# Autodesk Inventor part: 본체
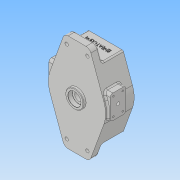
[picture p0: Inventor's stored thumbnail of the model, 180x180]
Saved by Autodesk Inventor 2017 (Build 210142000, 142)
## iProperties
Part Number: 본체
Material: 일반
Document SubType Name: Modeling
Designer: MRC
Density: 1 g/cm^3
Appearance: 기본값
Author: MRC
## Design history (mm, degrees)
sketch "스케치1"
  geometry: L1 (-51.683, 18.811)-(-33.78, 68); L2 (-24.317, 94)-(0, 94); L3 (0, 0)-(0, 94); L4 (0, 0)-(-58.53, 0); L5 (51.683, 18.811)-(33.78, 68); L6 (24.317, 94)-(0, 94); L7 (-51.683, -18.811)-(-33.78, -68); L8 (-24.317, -94)-(0, -94); L9 (51.683, -18.811)-(33.78, -68); L10 (24.317, -94)-(0, -94); L11 (-33.78, 68)-(33.78, 68); L12 (-33.78, -68)-(33.78, -68); L13 (-33.78, 68)-(-24.317, 94); L14 (33.78, 68)-(24.317, 94); L15 (33.78, -68)-(24.317, -94); L16 (-33.78, -68)-(-24.317, -94); A1 r 55 centre (0, 0) between (-51.683, 18.811) and (-51.683, -18.811); A2 r 55 centre (0, 0) between (51.683, -18.811) and (51.683, 18.811); 1 further point
  constraints: 32 end point, 8 tangent, 4 point on circle, 4 symmetric about line, 3 horizontal, 2 centre point, 1 coincident, 1 parallel, 1 vertical, 1 vertical alignment
  dimensions: "d3" = 20 deg angle of L3 L1; "d4" = 94 distance from line of point (0, 0) L2; "d6" = 136 distance between parallel lines of L12 L11; "d7" = 68 distance from line of L11 point (0, 0); "d8" = 55 radius of A2; "d9" = 55 radius of A1
extrude "돌출1" new body sketch "스케치1" distance "d10" = 15; taper "d11" = 0 deg
extrude "돌출2" join sketch "스케치1" distance "d12" = 55; taper "d13" = 0 deg
sketch "스케치3"
  geometry: C1 r 17.5 at (0, 0); A1 r 55 centre (0, 0) between (-51.683, 18.811) and (-51.683, -18.811) reference
  constraints: 1 centre point, 1 coincident
  dimensions: "d22" = 35 diameter of C1
extrude "돌출4" join sketch "스케치3" distance "d23" = 5; taper "d24" = 0 deg
sketch "스케치4"
  geometry: L1 (-68, 15)-(-68, 55) reference; L2 (-68, 55)-(68, 55) reference; L3 (68, 55)-(68, 15) reference; L4 (68, 15)-(94, 15) reference; L5 (94, 15)-(94, 0) reference; L6 (94, 0)-(17.5, 0) reference; L7 (17.5, 0)-(17.5, -5) reference; L8 (17.5, -5)-(-17.5, -5) reference; L9 (-17.5, -5)-(-17.5, 0) reference; L10 (-17.5, 0)-(-94, 0) reference; L11 (-94, 0)-(-94, 15) reference; L12 (-94, 15)-(-68, 15) reference; L13 (-9, 5)-(27, 5); L14 (32, 10)-(32, 30); L15 (27, 35)-(-9, 35); L16 (-14, 30)-(-14, 10); L17 (9, 5)-(9, 35); A1 r 5 centre (27, 30) between (32, 30) and (27, 35); A2 r 5 centre (-9, 30) between (-9, 35) and (-14, 30); A3 r 5 centre (-9, 10) between (-14, 10) and (-9, 5); A4 r 5 centre (27, 10) between (27, 5) and (32, 10); 4 further points
  constraints: 10 end point, 8 point on circle, 8 tangent, 6 point on line, 4 centre point, 3 equal radius, 2 midpoint, 2 parallel, 1 horizontal, 1 perpendicular
  dimensions: "d25" = 9 distance from line of point (0, 0) L17; "d26" = 30 distance of point (32, 5) point (32, 35); "d27" = 46 distance of point (32, 35) point (-14, 35); "d28" = 5 distance between parallel lines of L13 L6; "d29" = 5 radius of A1 (derived)
extrude "돌출5" join sketch "스케치4" stored distance "d30" = 118; taper "d31" = 0 deg
sketch "스케치5"
  geometry: A1 r 55 centre (0, 0) between (51.683, -18.811) and (51.683, 18.811) reference; 1 further point
  constraints: 1 vertical alignment
  dimensions: "d32" = 9 distance of A1.centre point (0, 9)
hole "구멍1" sketch "스케치5" at (0, 9) diameter "d33" = 80; stored, may be unused: countersink angle "d37" = 90 deg, drill point angle "d39" = 0 deg; dims "d34" = 6, "d35" = 4, "d36" = 2, "d38" = 30
node "작업 평면1"
sketch "스케치6"
  geometry: L1 (-40, 55)-(40, 55) reference; L2 (0, 55)-(0, 28.705); L3 (-33.78, 55)-(-51.683, 55) reference; L4 (-47.5, 55)-(-47.5, 53.1); L5 (-47, 52.6)-(-43.9, 52.6); L6 (-43.4, 53.1)-(-43.4, 55); L7 (-43.4, 55)-(-47.5, 55); A1 r 0.5 centre (-43.9, 53.1) between (-43.9, 52.6) and (-43.4, 53.1); A2 r 0.5 centre (-47, 53.1) between (-47.5, 53.1) and (-47, 52.6); 2 further points
  constraints: 10 end point, 4 point on circle, 4 point on line, 4 tangent, 3 perpendicular, 2 centre point, 2 vertical, 1 equal radius, 1 midpoint
  dimensions: "d41" = 95 diameter of L4 L2; "d42" = 4.1 distance between parallel lines of L4 L6; "d43" = 2.4 distance of point (-43.4, 52.6) L6.end; "d44" = 0.5 radius of A1
revolve "회전1" sketch "스케치6" stored, may be unused: angle "d45" = 90 deg
sketch "스케치7"
  geometry: L1 (17.5, 0)-(17.5, -5) reference; L2 (17.5, -5)-(-17.5, -5) reference; L3 (-17.5, -5)-(-17.5, 0) reference; L4 (-17.5, 0)-(-94, 0) reference; L5 (-94, 0)-(-94, 15) reference; L6 (-94, 15)-(-68, 15) reference; L7 (-68, 15)-(-68, 55) reference; L8 (-68, 55)-(-38.5, 55) reference; L9 (-38.5, 55)-(-38.5, 53.1) reference; L10 (-38, 52.6)-(-34.9, 52.6) reference; L11 (-34.4, 53.1)-(-34.4, 55) reference; L12 (-34.4, 55)-(-31, 55) reference; L13 (-31, 55)-(-31, 25) reference; L14 (-31, 25)-(49, 25) reference; L15 (49, 25)-(49, 55) reference; L16 (49, 55)-(52.4, 55) reference; L17 (52.4, 55)-(52.4, 53.1) reference; L18 (52.9, 52.6)-(56, 52.6) reference; L19 (56.5, 53.1)-(56.5, 55) reference; L20 (56.5, 55)-(68, 55) reference; L21 (68, 55)-(68, 15) reference; L22 (68, 15)-(94, 15) reference; L23 (94, 15)-(94, 0) reference; L24 (94, 0)-(17.5, 0) reference; L25 (49, 25)-(-31, 25) reference; L26 (0, 25)-(0, -5); L27 (0, 25)-(10, 25); L28 (10, 25)-(10, 15); L29 (10, 15)-(8, 15); L30 (8, 15)-(8, 3.4); L31 (-9, 5)-(18.811, 5) reference; L32 (8, 3.4)-(12.3, 3.4); L33 (12.5, 3.2)-(12.5, -5); L34 (0, -5)-(12.5, -5); L35 (-17.5, -5)-(17.5, -5) reference; L36 (10, 25)-(0, 25); A1 r 0.5 centre (-38, 53.1) between (-38.5, 53.1) and (-38, 52.6) reference; A2 r 0.5 centre (-34.9, 53.1) between (-34.9, 52.6) and (-34.4, 53.1) reference; A3 r 0.5 centre (52.9, 53.1) between (52.4, 53.1) and (52.9, 52.6) reference; A4 r 0.5 centre (56, 53.1) between (56, 52.6) and (56.5, 53.1) reference; A5 r 0.2 centre (12.3, 3.2) between (12.5, 3.2) and (12.3, 3.4); 2 further points
  constraints: 18 end point, 5 point on line, 4 perpendicular, 2 point on circle, 2 tangent, 2 vertical, 1 centre point, 1 collinear, 1 midpoint, 1 parallel
  dimensions: "d46" = 20 diameter of L28 L26; "d47" = 16 diameter of L30 L26; "d48" = 25 diameter of L33 L26; "d49" = 10 distance of L27.end L28.end; "d50" = 8.4 distance of point (12.5, 3.4) L33.end; "d51" = 0.2 radius of A5
revolve "회전2" sketch "스케치7" stored, may be unused: angle "d52" = 90 deg
chamfer "모따기1" distance "d53" = 0.4; stored, may be unused: second distance "d54" = 2, angle "d55" = 30 deg
sketch "스케치8"
  geometry: L1 (-26.702, 6)-(-22.517, 6); L2 (-26.702, -6)-(-25.515, -6); L3 (-23.812, -6)-(23.812, -6); L4 (-18.735, 6)-(18.735, 6); L5 (22.517, 6)-(26.702, 6); L6 (25.515, -6)-(26.702, -6); C1 r 40 at (0, 0) reference; C2 r 8 at (0, -9) reference; A1 r 29 centre (0, 0) between (-28.373, -6) and (28.373, -6); A2 r 24 centre (0, -9) between (-20.785, 3) and (-23.552, -4.385); A3 r 29 centre (0, 0) between (-28.68, 4.296) and (-28.68, -4.296); A4 r 24 centre (0, -9) between (18.735, 6) and (-18.735, 6); A5 r 29 centre (0, 0) between (28.373, 6) and (-28.373, 6); A6 r 29 centre (0, 0) between (28.68, -4.296) and (28.68, 4.296); A7 r 24 centre (0, -9) between (23.552, -4.385) and (20.785, 3); A8 r 24 centre (0, -9) between (-23.812, -6) and (23.812, -6); A9 r 2 centre (-22.517, 4) between (-20.785, 3) and (-22.517, 6); A10 r 2 centre (-26.702, 4) between (-26.702, 6) and (-28.68, 4.296); A11 r 2 centre (-26.702, -4) between (-28.68, -4.296) and (-26.702, -6); A12 r 2 centre (-25.515, -4) between (-25.515, -6) and (-23.552, -4.385); A13 r 2 centre (25.515, -4) between (23.552, -4.385) and (25.515, -6); A14 r 2 centre (26.702, -4) between (26.702, -6) and (28.68, -4.296); A15 r 2 centre (26.702, 4) between (28.68, 4.296) and (26.702, 6); A16 r 2 centre (22.517, 4) between (22.517, 6) and (20.785, 3)
  constraints: 42 point on circle, 16 centre point, 16 tangent, 12 end point, 8 point on line, 7 equal radius, 6 horizontal, 2 coincident
  dimensions: "d56" = 58 diameter of A1; "d57" = 48 diameter of A2; "d58" = 6 distance from line of L2 C1.centre; "d59" = 6 distance from line of C1.centre L1; "d60" = 2 radius of A9
extrude "돌출6" cut sketch "스케치8" distance "d61" = 12; taper "d62" = 0 deg
sketch "스케치9"
  geometry: L1 (-5, -9)-(-5, 27) reference; L2 (-29, -8)-(-11, -8); L3 (-11, -8)-(-11, 26); L4 (-11, 26)-(-29, 26); L5 (-29, 26)-(-29, -8); L6 (-29, -8)-(-11, 26); L7 (-11, -8)-(-29, 26); 7 further points
  constraints: 12 end point, 5 coincident, 2 midpoint, 2 parallel, 1 horizontal, 1 perpendicular
  dimensions: "d63" = 9 vertical distance of point (0, 0) point (-20, 9); "d64" = 15 distance from line of L1 point (-20, 9); "d65" = 18 distance of L3.end L4.end; "d66" = 34 distance of L2.end L3.end
hole "구멍2" sketch "스케치9" diameter "d67" = 3.242; stored, may be unused: countersink angle "d71" = 90 deg, drill point angle "d73" = 118 deg; dims "d68" = 8, "d69" = 4, "d70" = 2, "d72" = 10
hole "구멍3" sketch "스케치9" diameter "d74" = 6; stored, may be unused: countersink angle "d78" = 90 deg, drill point angle "d80" = 118 deg; dims "d75" = 8, "d76" = 4, "d77" = 2, "d79" = 10
sketch "스케치10"
  geometry: A1 r 29 centre (0, 0) between (-28.68, 4.296) and (-28.68, -4.296) reference; 2 further points
  constraints: 1 horizontal alignment
  dimensions: "d81" = 30 distance of point (15, 17) point (-15, 17); "d82" = 17 vertical distance of A1.centre point (15, 17); "d83" = 15 horizontal distance of A1.centre point (-15, 17)
hole "구멍4" sketch "스케치10" at (-15, 17), (15, 17) diameter "d84" = 3.242; stored, may be unused: countersink angle "d88" = 90 deg, drill point angle "d90" = 118 deg; dims "d85" = 8, "d86" = 4, "d87" = 2, "d89" = 10
sketch "스케치11"
  geometry: L1 (-22.517, 15)-(-26.702, 15) reference; L2 (-26.702, 3)-(-25.515, 3) reference; L3 (25.515, 3)-(26.702, 3) reference; L4 (26.702, 15)-(22.517, 15) reference; L5 (33.78, -68)-(-33.78, -68) reference; L6 (-24.317, -94)-(-33.78, -68) reference; L7 (24.317, -94)-(-24.317, -94) reference; L8 (33.78, -68)-(24.317, -94) reference; L9 (51.683, -18.811)-(33.78, -68) reference; L10 (59, -14)-(53.188, -14) reference; L11 (59, 32)-(59, -14) reference; L12 (46.883, 32)-(59, 32) reference; L13 (33.78, 68)-(46.883, 32) reference; L14 (-33.78, 68)-(33.78, 68) reference; L15 (-33.78, 68)-(-24.317, 94) reference; L16 (-24.317, 94)-(24.317, 94) reference; L17 (24.317, 94)-(33.78, 68) reference; L18 (-33.78, -68)-(-51.683, -18.811) reference; L19 (-53.188, -14)-(-59, -14) reference; L20 (-59, -14)-(-59, 32) reference; L21 (-59, 32)-(-46.883, 32) reference; L22 (-46.883, 32)-(-33.78, 68) reference; L23 (-20, -79)-(20, -79); L24 (20, -79)-(20, 79); L25 (20, 79)-(-20, 79); L26 (-20, 79)-(-20, -79); L27 (-20, -79)-(20, 79); L28 (20, -79)-(-20, 79); C1 r 10 at (0, 0) reference; C2 r 8 at (0, 0) reference; C3 r 1.621 at (-15, 26) reference; C4 r 1.621 at (15, 26) reference; A1 r 2 centre (-26.702, 13) between (-26.702, 15) and (-28.68, 13.296) reference; A2 r 29 centre (0, 9) between (-28.68, 13.296) and (-28.68, 4.704) reference; A3 r 2 centre (-26.702, 5) between (-28.68, 4.704) and (-26.702, 3) reference; A4 r 2 centre (-25.515, 5) between (-25.515, 3) and (-23.552, 4.615) reference; A5 r 24 centre (0, 0) between (-20.785, 12) and (-23.552, 4.615) reference; A6 r 2 centre (-22.517, 13) between (-20.785, 12) and (-22.517, 15) reference; A7 r 2 centre (26.702, 5) between (26.702, 3) and (28.68, 4.704) reference; A8 r 29 centre (0, 9) between (28.68, 4.704) and (28.68, 13.296) reference; A9 r 2 centre (26.702, 13) between (28.68, 13.296) and (26.702, 15) reference; A10 r 2 centre (22.517, 13) between (22.517, 15) and (20.785, 12) reference; A11 r 24 centre (0, 0) between (23.552, 4.615) and (20.785, 12) reference; A12 r 2 centre (25.515, 5) between (23.552, 4.615) and (25.515, 3) reference; A13 r 55 centre (0, 0) between (51.683, -18.811) and (53.188, -14) reference; A14 r 55 centre (0, 0) between (-53.188, -14) and (-51.683, -18.811) reference; 5 further points
  constraints: 12 end point, 4 coincident, 2 midpoint, 2 parallel, 1 horizontal, 1 perpendicular
  dimensions: "d91" = 40 distance of L25.end L24.end; "d92" = 158 distance of L24.end L23.end
hole "구멍5" sketch "스케치11" at (-20, 79), (20, 79), (20, -79), (-20, -79) diameter "d93" = 6.6; stored, may be unused: countersink angle "d97" = 90 deg, drill point angle "d99" = 118 deg; dims "d94" = 8, "d95" = 11, "d96" = 6.6, "d98" = 10
sketch "스케치12"
  geometry: L1 (-25, -61)-(25, -61); L2 (25, -61)-(25, 61); L3 (25, 61)-(-25, 61); L4 (-25, 61)-(-25, -61); L5 (-25, -61)-(25, 61); L6 (25, -61)-(-25, 61); A1 r 55 centre (0, 0) between (-51.683, 18.811) and (-51.683, -18.811) reference; 4 further points
  constraints: 12 end point, 4 coincident, 2 midpoint, 2 parallel, 1 horizontal, 1 perpendicular
  dimensions: "d100" = 50 distance of L3.end L2.end; "d101" = 122 distance of L2.end L1.end
hole "구멍6" sketch "스케치12" at (-25, 61), (25, 61), (25, -61), (-25, -61) diameter "d102" = 4.917; stored, may be unused: countersink angle "d106" = 90 deg, drill point angle "d108" = 118 deg; dims "d103" = 12, "d104" = 11, "d105" = 6.6, "d107" = 14
sketch "스케치13"
  geometry: L1 (67.56, -40)-(0, -40) reference; L2 (8.892, -21.398)-(58.667, -21.398); L3 (58.667, -21.398)-(58.667, -28.602); L4 (58.667, -28.602)-(8.892, -28.602); L5 (8.892, -28.602)-(8.892, -21.398); L6 (8.892, -25)-(58.667, -25); L7 (33.78, -21.398)-(33.78, -28.602); 1 further point
  constraints: 4 end point, 4 midpoint, 1 vertical alignment, 2 other
  dimensions: "d109" = 15 distance from line of L1 L6.start
feature "엠보싱1" sketch "스케치13" dims "d3" = 20 deg, "d4" = 94, "d6" = 136, "d7" = 68, "d8" = 55, "d9" = 55, "d110" = 0.5, "d111" = 0
fillet "모깎기1" dims "d112" = 2
fillet "모깎기2" dims "d113" = 10
fillet "모깎기3" dims "d114" = 3
fillet "모깎기4" dims "d115" = 3
chamfer "모따기2" distance "d116" = 1; stored, may be unused: second distance "d117" = 2, angle "d118" = 30 deg
node "솔리드1"
mirror "미러1"
mirror "미러2"
node "절단 모서리 투영2"
node "절단 모서리 투영3"
node "절단 모서리 투영4"
other parameters: "d40" = 9
